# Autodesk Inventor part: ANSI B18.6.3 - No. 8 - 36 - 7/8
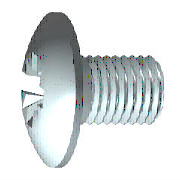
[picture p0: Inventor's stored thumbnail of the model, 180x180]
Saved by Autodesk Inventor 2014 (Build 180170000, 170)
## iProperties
IsCustomPart: 0
Created: 2010-12
Part Number: ANSI B18.6.3 - No. 8 - 36 - 7/8
Material: Steel, Mild
Description: Cross Recessed Truss Head Machine Screw - Type IA
Document SubType Name: Modeling
Standard: ANSI B18.6.3
Designer: Beta-8540w
Standard Revision: 2003
Standards Organization: ANSI
Language: en-US
Size Designation: No. 8 - 36 - 7/8
Categories: <MemberInstance><Categories><Category DisplayName="Fasteners" InternalName="e4da775c-781d-43d5-af7c-5136215cf5a6" Mnemonic="FSTN"><Category DisplayName="Bolts"
Density: 7.86 g/cm^3
Appearance: Steel
Mass: 3.23362 g
Surface Area: 4.81457 cm^2
Volume: 0.411402 cm^3
Author: Beta-8540w
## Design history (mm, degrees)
workplane "Work Plane3"
sketch "Sketch4"
  geometry: L1 (-9, 0)-(9, 0) reference; L2 (0, -9)-(0, 9) reference; L3 (0, 0)-(6.428, 6.428); L4 (0, 0)-(6.428, -6.428); L5 (0, 0)-(-6.428, 6.428); L6 (0, 0)-(-6.428, -6.428); L7 (1.392, 1.392)-(0, 0.26); L8 (-1.392, 1.392)-(-0.26, 0); L9 (-1.392, -1.392)-(0, -0.26); L10 (1.392, -1.392)-(0.26, 0); L11 (1.392, 1.392)-(0.26, 0); L12 (-1.392, 1.392)-(0, 0.26); L13 (-1.392, -1.392)-(-0.26, 0); L14 (1.392, -1.392)-(0, -0.26); C1 r 4.877 at (0, 0) reference; A1 r 0.26 centre (0, 0) between (0, 0.26) and (0, -0.26); A2 r 1.968 centre (0, 0) between (1.392, 1.392) and (1.392, -1.392); 1 further point
  constraints: 25 end point, 7 point on circle, 7 point on line, 3 symmetric about line, 2 centre point, 2 coincident, 2 perpendicular, 3 other
  dimensions: "d11" = 0.5207 diameter of A1 (= 0.5 x SBR); "d14" = 45 deg angle of L3 L1; "d29" = 1.39194 distance from line of L1 L7.start (= 0.353553 x SDM)
extrude "Star Cut" cut sketch "Sketch4" distance "d12" = 2.5908 (= KOH); taper "d13" = -30 deg
sketch "Sketch2"
  geometry: L1 (-7.196, 0)-(9.04, 0) reference; L2 (0, -7.196)-(0, 9.04) reference; L3 (0, 1.969)-(0, 0); L4 (0, 0)-(1.968, 0); L5 (0, 0)-(6.721, 6.721); L6 (0.521, 1.898)-(0.297, 0.938); L7 (1.898, 0.521)-(0.938, 0.297); L8 (1.898, -0.521)-(0.938, -0.297); L9 (0.521, -1.898)-(0.297, -0.938); L10 (-0.521, 1.898)-(-0.297, 0.938); L11 (-1.898, 0.521)-(-0.938, 0.297); L12 (-0.521, -1.898)-(-0.297, -0.938); L13 (-1.898, -0.521)-(-0.938, -0.297); C1 r 4.877 at (0, 0) reference; A1 r 0.787 centre (0, 0) between (0.787, 0) and (0, 0.787); A2 r 0.245 centre (0.536, 0.883) between (0.297, 0.938) and (0.709, 0.709); A3 r 0.245 centre (0.883, 0.536) between (0.709, 0.709) and (0.938, 0.297); A4 r 1.968 centre (0, 0) between (1.968, 0) and (1.898, 0.521); A5 r 1.968 centre (0, 0) between (0.521, 1.898) and (0, 1.969); A6 r 1.968 centre (0, 0) between (1.898, 0.521) and (0.521, 1.898); A7 r 1.968 centre (0, 0) between (0, -1.969) and (0.521, -1.898); A8 r 1.968 centre (0, 0) between (0.521, -1.898) and (1.898, -0.521); A9 r 1.968 centre (0, 0) between (1.898, -0.521) and (1.968, 0); A10 r 0.245 centre (0.536, -0.883) between (0.709, -0.709) and (0.297, -0.938); A11 r 0.245 centre (0.883, -0.536) between (0.938, -0.297) and (0.709, -0.709); A12 r 0.245 centre (-0.536, 0.883) between (-0.709, 0.709) and (-0.297, 0.938); A13 r 0.245 centre (-0.883, 0.536) between (-0.938, 0.297) and (-0.709, 0.709); A14 r 1.968 centre (0, 0) between (-1.898, 0.521) and (-1.968, 0); A15 r 1.968 centre (0, 0) between (-0.521, 1.898) and (-1.898, 0.521); A16 r 1.968 centre (0, 0) between (0, 1.969) and (-0.521, 1.898); A17 r 1.968 centre (0, 0) between (-1.968, 0) and (-1.898, -0.521); A18 r 1.968 centre (0, 0) between (-1.898, -0.521) and (-0.521, -1.898); A19 r 1.968 centre (0, 0) between (-0.521, -1.898) and (0, -1.969); A20 r 0.245 centre (-0.883, -0.536) between (-0.709, -0.709) and (-0.938, -0.297); A21 r 0.245 centre (-0.536, -0.883) between (-0.297, -0.938) and (-0.709, -0.709); A22 r 0.984 centre (0, 0) between (0.984, 0) and (0, 0.984)
  constraints: 46 point on circle, 25 symmetric about line, 22 centre point, 22 end point, 6 tangent, 4 coincident, 3 collinear, 3 point on line, 1 midpoint, 1 perpendicular, 22 other
  dimensions: "d4" = 45 deg angle of L5 L4; "d5" = 1.5748 diameter of A1 (= 0.4 x SDM); "d6" = 3.937 diameter of A6 (= SDM); "d7" = 0.5207 distance from line of L6.start L3 (= 0.5 x SBR); "d20" = 1.9685 diameter of A22 (= 0.5 x SDM)
extrude "Slot" join sketch "Sketch2" taper "d21" = 0 deg; stored distance "d54" = 10
revolve "Cut" stored, may be unused: angle "d56" = 90 deg
revolve "Body" stored, may be unused: angle "d18" = 90 deg
node "IDS_WORKPLANE{1}"
body "Solid1"
sketch "Sketch1"
  geometry: L1 (22.225, 0)-(22.225, 2.083); L2 (22.225, 2.083)-(0, 2.083); L3 (3.962, 5.08)-(3.962, 5.08); L4 (-2.591, 0)-(-2.591, 4.877); L5 (-2.324, 1.836)-(-1.077, 1.214); L6 (-1.077, 1.214)-(-0.432, 0); L7 (-0.432, 0)-(22.225, 0); L8 (-8.191, 0)-(27.294, 0) reference; L9 (0, -1.024)-(0, 6.143) reference; L10 (-2.324, 1.836)-(-2.591, 1.968); L11 (-0.363, 4.877)-(-2.591, 4.877); L12 (-0.363, 4.877)-(0, 4.877); L13 (0, 4.877)-(0, 2.083); A1 r 6.452 centre (3.861, 0) between (-0.363, 4.877) and (-2.591, 0)
  constraints: 22 end point, 4 collinear, 4 point on circle, 3 point on line, 2 parallel, 2 perpendicular, 1 centre point, 1 horizontal, 1 tangent
  dimensions: "d1" = 4.1656 diameter of L2 L7 (= GD); "d2" = 2.159 distance from line of L6.end L4 (= STI); "d16" = 3.937 diameter of L10.end L7 (= SDM); "d17" = 62 deg angle of L6 L7; "d19" = 26.5 deg angle of L5 L7; "d23" = 9.7536 diameter of L12.end L7 (= KOD); "d25" = 2.5908 distance between parallel lines of L4 L13 (= KOH); "d26" = 6.4516 radius of A1 (= KR); "d28" = 22.225 distance between parallel lines of L1 L13 (= NLG)
fillet "Fillet1" dims "d22" = 0.20828 (= 0.2 x SBR)
feature "Thread" dims "d8" = 20.46122 (= GEL), "d9" = 0
chamfer "Chamfer" distance "d78" = 0.35278 (= 0.5 x RR); stored, may be unused: second distance "d79" = 2, angle "d80" = 45 deg
other parameters: "GD" = 4.1656 (= NND) [user parameter; used in 1 equation term], "NLG" = 22.225 [user parameter; used in 1 equation term], "GEL" = 20.46122 [user parameter; used in 1 equation term], "KOD" = 9.7536 [user parameter; used in 1 equation term], "KOH" = 2.5908 [user parameter; used in 3 equation terms], "SDM" = 3.937 [user parameter; used in 5 equation terms], "STI" = 2.159 [user parameter; used in 1 equation term], "SBR" = 1.0414 [user parameter; used in 3 equation terms], "d3" = -2.5908 (= -KOH), "d10" = 0, "KR" = 6.4516 [user parameter; used in 1 equation term], "d75" = 0, "d76" = 0, "RR" = 0.70556 (computed from TPU) [user parameter; used in 1 equation term], "GUL" = 0 [user parameter], "SPD" = 3.40106 [user parameter], "PTC" = 0.70556 (computed from TPU) [user parameter], "THREADDIA" = 4.1656 [user parameter], "TOA" = 30 deg [user parameter], "BDM" = 4.1656 (= NND) [user parameter], "NND" = 4.1656 [user parameter; used in 2 equation terms], "GAL" = 0.70612 [user parameter], "GD1" = 3.40106 [user parameter]
